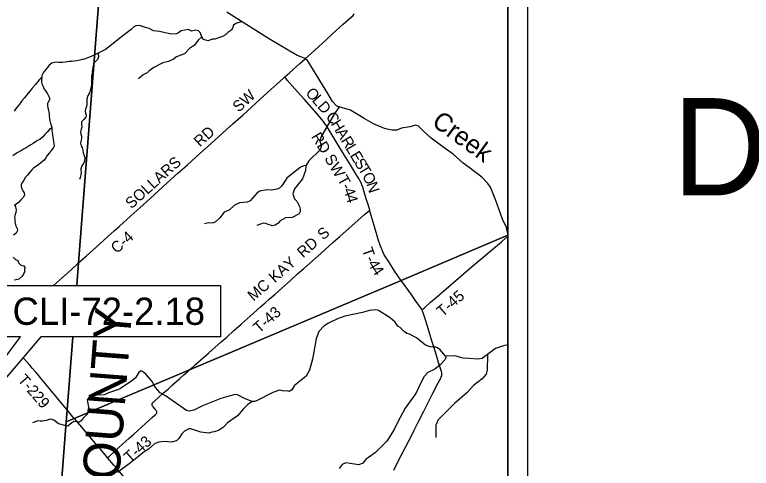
# Model space of a CAD drawing. Extents: x 0 to 34, y 0 to 22.
# Drawn here: x 6.367 to 10.15, y 18.098 to 20.428 of the extents above; entities that cross this region are included whole.
import ezdxf

# ---------------------------------------------------------------- set-up
doc = ezdxf.new("R2010")
doc.units = 0
for name, color, linetype in [('Default', 7, 'Continuous'), ('GM_X_County_Road', 7, 'Continuous'), ('GM_X_County_Road_Text', 7, 'Continuous'), ('GM_X_County_Text', 7, 'Continuous'), ('GM_X_Minor_River', 7, 'Continuous'), ('GM_X_Minor_River_Text', 7, 'Continuous'), ('GM_X_Township_Road', 7, 'Continuous'), ('GM_X_Township_Road_Text', 7, 'Continuous'), ('SH_Cut_Line', 7, 'Continuous'), ('SH_Data', 7, 'Continuous'), ('SH_Text', 7, 'Continuous')]:
    doc.layers.add(name, color=color, linetype=linetype)

msp = doc.modelspace()

# ---------------------------------------------------------------- linework, layer by layer
at = {"layer": 'Default'}
for points in [[(6.6858, 19.0362), (6.6949, 19.1537), (6.8302, 20.9), (3.1229, 20.9), (2.9275, 20.8467), (2.2946, 20.6707), (2.1, 20.6202), (2.1, 17.1279), (2.1211, 17.1003), (3.2076, 15.5689), (3.4902, 15.1704), (4.0558, 14.3671), (4.1658, 14.2105), (4.302, 14.3105), (5.6165, 15.2674), (6.0871, 15.6176), (6.2834, 15.7529), (6.4392, 15.8657), (6.5428, 17.1931), (6.5451, 17.2211), (6.6309, 18.3364), (6.6363, 18.3979), (6.6654, 18.7733)], [(6.6654, 18.7733), (6.6363, 18.3979), (6.6309, 18.3364), (6.6732, 18.3539), (7.2653, 18.6041), (8.3519, 19.0632), (8.9, 19.2947), (8.9, 20.9), (6.8302, 20.9), (6.6949, 19.1537), (6.6858, 19.0362)]]:
    msp.add_lwpolyline(points, dxfattribs=at)
msp.add_lwpolyline([(8.9, 15.8067), (8.9, 19.2947), (8.3519, 19.0632), (7.2653, 18.6041), (6.6732, 18.3539), (6.6309, 18.3364), (6.5451, 17.2211), (6.5428, 17.1931), (6.4392, 15.8657), (6.5786, 15.8624), (7.3679, 15.8435), (8.1324, 15.8252)], close=True, dxfattribs=at)
at = {"layer": 'GM_X_County_Road'}
for points in [[(7.7542, 20.1084), (7.7776, 20.1293), (7.8307, 20.1771), (7.8584, 20.202), (7.8907, 20.2312), (7.9644, 20.2978), (8.0012, 20.3312), (8.0541, 20.3792), (8.0821, 20.4039), (8.0959, 20.4164), (8.1047, 20.4252), (8.1109, 20.4321)], [(6.6951, 19.1531), (6.735, 19.1889), (6.8019, 19.2493), (6.8411, 19.2847), (6.8781, 19.3179), (6.9035, 19.3407), (6.9637, 19.3946), (7.0096, 19.4365), (7.0624, 19.4845), (7.1499, 19.5638), (7.2054, 19.6136), (7.2538, 19.6572), (7.3186, 19.7153), (7.3763, 19.7672), (7.4546, 19.8382), (7.4868, 19.8674), (7.538, 19.9127), (7.5587, 19.9314), (7.6276, 19.9941), (7.683, 20.044), (7.713, 20.0711), (7.7475, 20.1024), (7.7542, 20.1084)], [(6.6734, 18.3534), (6.6714, 18.3558), (6.6365, 18.3974)], [(6.8443, 18.1514), (6.84, 18.1565), (6.8077, 18.1951), (6.7824, 18.2248), (6.7536, 18.2586), (6.7281, 18.2885), (6.7012, 18.3201), (6.6734, 18.3534)], [(7.1522, 17.7843), (7.1477, 17.7899), (7.1124, 17.8328), (7.0863, 17.8644), (7.0586, 17.898), (7.0311, 17.9314), (6.9967, 17.972), (6.9634, 18.0116), (6.9288, 18.0526), (6.901, 18.0848), (6.8762, 18.1141), (6.8443, 18.1514)]]:
    msp.add_lwpolyline(points, dxfattribs=at)
at = {"layer": 'GM_X_Minor_River'}
for points in [[(8.9, 19.3003), (8.8996, 19.3025), (8.8927, 19.3352), (8.8716, 19.3779), (8.8389, 19.4739), (8.8104, 19.5417), (8.7974, 19.5616), (8.767, 19.5941), (8.7004, 19.6437), (8.6704, 19.6661), (8.6197, 19.7125), (8.5719, 19.7441), (8.5068, 19.7948), (8.4644, 19.8309), (8.4397, 19.8578), (8.4279, 19.8613), (8.3968, 19.8525), (8.3531, 19.8457), (8.3417, 19.8409), (8.3291, 19.8354), (8.3041, 19.8349), (8.267, 19.844), (8.2093, 19.8681), (8.161, 19.8944), (8.0925, 19.9387), (8.0211, 19.9584), (7.9997, 19.9829), (7.9759, 20.023), (7.8887, 20.1662), (7.8704, 20.1925), (7.8569, 20.2029), (7.8414, 20.2095), (7.8169, 20.2185), (7.6704, 20.3054), (7.4806, 20.4261), (7.4573, 20.4423)], [(7.5296, 20.3921), (7.5021, 20.383), (7.4903, 20.3751), (7.4821, 20.3506), (7.4622, 20.3375), (7.4503, 20.3255), (7.4351, 20.3169), (7.3951, 20.3021), (7.3822, 20.3034), (7.3586, 20.2938), (7.3367, 20.3008), (7.3278, 20.3142), (7.3196, 20.3363), (7.3107, 20.3463), (7.2974, 20.349), (7.2746, 20.3447), (7.2595, 20.3517), (7.2227, 20.3464), (7.2086, 20.3348), (7.1975, 20.3296), (7.1698, 20.328), (7.1101, 20.343), (7.0805, 20.3463), (7.0583, 20.3568), (7.033, 20.3643), (7.0088, 20.3725), (6.9887, 20.3708), (6.9788, 20.3656), (6.9654, 20.3517), (6.9222, 20.3206), (6.8495, 20.2614), (6.8327, 20.2491), (6.7779, 20.2222)], [(7.3278, 20.3142), (7.309, 20.2977), (7.2909, 20.2713), (7.2646, 20.2541), (7.2396, 20.2271), (7.1981, 20.2127), (7.1821, 20.2), (7.1573, 20.1881), (7.1281, 20.1819), (7.0819, 20.1574), (7.0571, 20.1402), (7.0468, 20.1289), (7.0266, 20.1188), (7.0021, 20.0982)], [(6.7779, 20.2222), (6.7626, 20.2146), (6.7508, 20.2097), (6.7382, 20.2049), (6.7249, 20.2008), (6.7131, 20.1975), (6.7009, 20.1949), (6.6861, 20.192), (6.6713, 20.1894), (6.658, 20.1888), (6.6466, 20.1877), (6.6359, 20.1871), (6.6257, 20.1849), (6.612, 20.1831), (6.6025, 20.1827), (6.5911, 20.1836), (6.5816, 20.184), (6.5713, 20.1834), (6.5576, 20.1789), (6.5443, 20.1695), (6.5347, 20.1574), (6.5236, 20.1431), (6.5136, 20.1295), (6.507, 20.1159), (6.5058, 20.106), (6.5049, 20.0935), (6.5045, 20.0836), (6.507, 20.073), (6.5123, 20.0623), (6.5186, 20.0463), (6.5261, 20.0349), (6.5347, 20.0215), (6.543, 20.0085), (6.5467, 19.9945), (6.5405, 19.9816), (6.5362, 19.9714), (6.5362, 19.9619), (6.5372, 19.9505), (6.5402, 19.9379), (6.5427, 19.9277), (6.5434, 19.9182), (6.5437, 19.9072), (6.5451, 19.8954), (6.5481, 19.8824), (6.5506, 19.8695), (6.5558, 19.8562), (6.5573, 19.8467), (6.5576, 19.8341), (6.5586, 19.8224), (6.5604, 19.8129), (6.5634, 19.7992), (6.5652, 19.7866), (6.5688, 19.7661), (6.5691, 19.7532), (6.5644, 19.7418), (6.5549, 19.7309), (6.5445, 19.7169), (6.5338, 19.7052), (6.5268, 19.6928), (6.518, 19.6814), (6.5073, 19.672), (6.4916, 19.6592), (6.4787, 19.6506), (6.466, 19.6408), (6.4561, 19.6337), (6.4439, 19.6197), (6.4327, 19.6038), (6.4228, 19.5929), (6.4132, 19.5789), (6.4066, 19.5683), (6.4004, 19.5551), (6.4004, 19.5452), (6.4033, 19.5331), (6.4089, 19.5235), (6.416, 19.5125), (6.4167, 19.5026), (6.4125, 19.4912), (6.3979, 19.4765), (6.3857, 19.4633), (6.3746, 19.4543), (6.3639, 19.4468)], [(6.7962, 20.2312), (6.7965, 20.2271), (6.7978, 20.2119), (6.7943, 20.1998), (6.7747, 20.1803)], [(6.7747, 20.1803), (6.7729, 20.1762), (6.7706, 20.1663), (6.769, 20.1561), (6.7666, 20.1451), (6.765, 20.1348), (6.7642, 20.1246), (6.7622, 20.1125), (6.7613, 20.103), (6.7609, 20.0923), (6.7607, 20.0692), (6.7602, 20.0589), (6.7571, 20.0457), (6.7536, 20.0317), (6.7478, 20.0195), (6.7416, 20.0093), (6.7369, 19.9942), (6.7376, 19.9801), (6.7379, 19.9684), (6.7363, 19.9574), (6.7305, 19.9437), (6.7281, 19.9339), (6.7314, 19.9217), (6.7336, 19.9118), (6.732, 19.9016), (6.7221, 19.8895), (6.7106, 19.8782), (6.7093, 19.8653), (6.7111, 19.8512), (6.7088, 19.841), (6.7056, 19.8262), (6.7059, 19.8141), (6.7096, 19.8045), (6.7099, 19.7928), (6.706, 19.7788), (6.7055, 19.7685), (6.7088, 19.7552), (6.7133, 19.7457), (6.7163, 19.7324), (6.7192, 19.7187), (6.724, 19.705), (6.7266, 19.6932), (6.7253, 19.6765), (6.721, 19.6632), (6.7111, 19.6511), (6.706, 19.6371), (6.7067, 19.6276), (6.7085, 19.617), (6.7073, 19.6056), (6.703, 19.5912), (6.6999, 19.581)], [(6.506, 20.1077), (6.4936, 20.0959), (6.484, 20.0834), (6.4736, 20.0698), (6.4575, 20.0513), (6.4456, 20.0374), (6.4364, 20.0253), (6.4268, 20.0151), (6.4169, 20.0015), (6.4042, 19.9856), (6.3969, 19.9758), (6.3858, 19.9615), (6.3747, 19.9479), (6.3647, 19.9324)], [(8.0337, 19.9543), (8.0081, 19.9168), (7.9386, 19.7984), (7.9339, 19.7791), (7.9423, 19.7558), (7.9364, 19.7347), (7.8782, 19.6772), (7.8627, 19.6523), (7.8598, 19.6281), (7.8457, 19.5846), (7.8035, 19.5342), (7.7948, 19.5073), (7.8033, 19.4829), (7.8153, 19.471), (7.8298, 19.4432), (7.8338, 19.4284), (7.8325, 19.4162), (7.8282, 19.4045), (7.7916, 19.3855), (7.7583, 19.3844), (7.7312, 19.3687), (7.7193, 19.3555), (7.7055, 19.3462), (7.6911, 19.3437), (7.6688, 19.3496), (7.656, 19.3558), (7.6439, 19.3574), (7.6108, 19.346)], [(6.5572, 19.8475), (6.5455, 19.838), (6.534, 19.8256), (6.5217, 19.8124), (6.5102, 19.7999), (6.4957, 19.7875), (6.4842, 19.7812), (6.4732, 19.7748), (6.461, 19.7658), (6.4491, 19.7598), (6.4369, 19.7515), (6.4251, 19.7451), (6.4125, 19.738), (6.4018, 19.7301), (6.3919, 19.7249), (6.3805, 19.7178), (6.3698, 19.7114), (6.3568, 19.7031)], [(7.8627, 19.6523), (7.8556, 19.6543), (7.835, 19.645), (7.7654, 19.5892), (7.7396, 19.5488), (7.7262, 19.5368), (7.7136, 19.5324), (7.6866, 19.5274), (7.6624, 19.5291), (7.6259, 19.5219), (7.6118, 19.5137), (7.5757, 19.4724), (7.5605, 19.4653), (7.521, 19.4623), (7.4947, 19.4474), (7.4706, 19.4264), (7.4436, 19.4145), (7.4205, 19.3848), (7.3991, 19.3649), (7.3876, 19.3585), (7.3743, 19.3564), (7.3619, 19.3588), (7.3417, 19.3545)], [(6.3698, 19.451), (6.371, 19.4395), (6.3744, 19.4258), (6.372, 19.4126), (6.3692, 19.4016), (6.3668, 19.3887), (6.3675, 19.3761), (6.3682, 19.3663), (6.3696, 19.3556), (6.3729, 19.3427), (6.38, 19.329), (6.3807, 19.3187), (6.3753, 19.3051), (6.3615, 19.2949)], [(6.3588, 19.1829), (6.3716, 19.1711), (6.3829, 19.1649), (6.3881, 19.1516), (6.3991, 19.1413), (6.4131, 19.1385), (6.4195, 19.129), (6.4179, 19.1172), (6.4174, 19.1066), (6.412, 19.0956), (6.4039, 19.0828), (6.3875, 19.0696), (6.3738, 19.0659), (6.3643, 19.0644)], [(8.9, 18.7312), (8.8995, 18.7315), (8.8767, 18.7275), (8.8371, 18.7124), (8.7676, 18.6611), (8.7444, 18.6576), (8.7009, 18.6618), (8.6709, 18.6636), (8.6267, 18.6755), (8.5801, 18.674), (8.5516, 18.707), (8.5392, 18.7173), (8.5294, 18.7193), (8.5161, 18.7202), (8.501, 18.7211), (8.4768, 18.7301), (8.4302, 18.7678), (8.3952, 18.7867), (8.3812, 18.7899), (8.3687, 18.7984), (8.3474, 18.8206), (8.3353, 18.8287), (8.3208, 18.8478), (8.2948, 18.8708), (8.2353, 18.9079), (8.2217, 18.911), (8.1872, 18.9076), (8.1655, 18.901), (8.1537, 18.8981), (8.0633, 18.8789), (8.0249, 18.8656), (7.9788, 18.8426), (7.954, 18.8276), (7.9286, 18.7998), (7.9161, 18.7635), (7.896, 18.659), (7.8806, 18.6023), (7.8636, 18.5709), (7.8036, 18.5237), (7.7905, 18.5011), (7.7767, 18.4929), (7.7658, 18.4953), (7.7517, 18.4943), (7.7271, 18.4983), (7.6933, 18.4873), (7.6094, 18.4445), (7.5984, 18.4401), (7.5862, 18.4402), (7.5645, 18.4256), (7.5396, 18.4016), (7.5119, 18.367), (7.4592, 18.3319), (7.4389, 18.3089), (7.4129, 18.291), (7.3912, 18.2847), (7.3798, 18.2837), (7.3646, 18.2786), (7.323, 18.2824), (7.2724, 18.3004), (7.261, 18.3009), (7.2389, 18.2882), (7.2262, 18.2754), (7.2096, 18.2509), (7.1981, 18.2385), (7.1727, 18.2316), (7.1348, 18.2354), (7.1071, 18.2326), (7.0862, 18.2245), (7.0536, 18.1956), (7.0265, 18.178), (7.0127, 18.1664), (6.9626, 18.1248), (6.8954, 18.0758)], [(8.5801, 18.674), (8.5819, 18.6661), (8.5772, 18.6559), (8.5527, 18.6288), (8.5248, 18.6074), (8.4893, 18.5896), (8.4698, 18.5693), (8.4531, 18.5365), (8.4271, 18.4821), (8.3717, 18.406), (8.3334, 18.3332), (8.3167, 18.2962), (8.2778, 18.2363), (8.2206, 18.1784), (8.1836, 18.153), (8.1737, 18.1485), (8.1545, 18.1245), (8.1351, 18.1159), (8.0684, 18.1257), (8.049, 18.1176), (8.034, 18.0957)], [(8.7952, 18.6824), (8.7942, 18.6017), (8.7887, 18.5816), (8.768, 18.5568), (8.724, 18.5231), (8.6899, 18.4851), (8.6256, 18.4304), (8.5413, 18.3459), (8.53, 18.3194), (8.5293, 18.2561)], [(7.5862, 18.4402), (7.5466, 18.4565), (7.5119, 18.4744), (7.4975, 18.4764), (7.4249, 18.4555), (7.3309, 18.4185), (7.2878, 18.3966), (7.2639, 18.3919), (7.2499, 18.3951), (7.1423, 18.4701), (7.1136, 18.4849), (7.09, 18.5128), (7.0777, 18.5334), (7.0733, 18.5429), (7.0415, 18.5797), (7.0291, 18.5912), (7.0163, 18.5978), (7.0037, 18.5892), (6.9867, 18.5628), (6.9733, 18.55), (6.9103, 18.507), (6.8996, 18.5018), (6.8532, 18.4871), (6.8258, 18.4749), (6.8019, 18.4725), (6.778, 18.4754), (6.7567, 18.471), (6.7387, 18.4488), (6.7473, 18.4006), (6.7456, 18.3877), (6.7383, 18.3745), (6.718, 18.3553), (6.7091, 18.3418), (6.6973, 18.3347), (6.6711, 18.3372), (6.6601, 18.3313), (6.6393, 18.3148), (6.6302, 18.3163)], [(6.6302, 18.3163), (6.6173, 18.3188), (6.6052, 18.3227), (6.5923, 18.3266), (6.5814, 18.3351), (6.5678, 18.3446), (6.5541, 18.3497), (6.5435, 18.3486), (6.5298, 18.3438), (6.5203, 18.3412), (6.5089, 18.339), (6.4986, 18.3402), (6.485, 18.3411), (6.472, 18.337), (6.4587, 18.3318)]]:
    msp.add_lwpolyline(points, dxfattribs=at)
at = {"layer": 'GM_X_Township_Road'}
for points in [[(8.1902, 19.4248), (8.1819, 19.4525), (8.1727, 19.4822), (8.1605, 19.524), (8.1549, 19.5418), (8.1505, 19.5534), (8.1456, 19.5648), (8.1401, 19.5759), (8.1341, 19.5868), (8.1244, 19.6027), (8.0934, 19.6529), (8.0512, 19.7219), (8.0269, 19.7616), (7.9961, 19.812), (7.9686, 19.8571), (7.96, 19.87), (7.9527, 19.88), (7.9429, 19.8921), (7.9183, 19.9201), (7.8549, 19.9926), (7.8199, 20.0322), (7.7666, 20.0929), (7.7587, 20.1025), (7.7568, 20.1049), (7.7542, 20.1084)], [(7.2811, 18.6177), (7.2952, 18.6301), (7.3232, 18.6547), (7.3626, 18.6898), (7.3952, 18.7186), (7.4279, 18.7473), (7.4558, 18.772), (7.493, 18.805), (7.5298, 18.8384), (7.5604, 18.8648), (7.5767, 18.8792), (7.6302, 18.9265), (7.6557, 18.9492), (7.6743, 18.9658), (7.7046, 18.9925), (7.7393, 19.0236), (7.7858, 19.0648), (7.8203, 19.0961), (7.8528, 19.1249), (7.911, 19.1764), (7.9387, 19.2014), (8.0013, 19.2572), (8.0361, 19.2882), (8.1317, 19.3724), (8.1641, 19.4015), (8.1826, 19.418), (8.1902, 19.4248)], [(8.3367, 19.0844), (8.3355, 19.086), (8.3198, 19.1091), (8.2826, 19.1664), (8.2712, 19.1849), (8.2636, 19.1985), (8.2581, 19.2096), (8.2518, 19.2238), (8.2459, 19.2382), (8.2417, 19.2499), (8.2362, 19.2677), (8.2133, 19.3452), (8.1935, 19.4139), (8.1902, 19.4248)], [(8.4585, 18.9127), (8.463, 18.916), (8.4655, 18.9178), (8.4727, 18.9237), (8.5029, 18.9505), (8.5335, 18.977), (8.5687, 19.0075), (8.6108, 19.0444), (8.6438, 19.0728), (8.6723, 19.0969), (8.6982, 19.1192), (8.7196, 19.1371), (8.741, 19.1552), (8.7719, 19.1813), (8.8053, 19.2092), (8.8668, 19.2616), (8.9, 19.2902)], [(6.567, 19.0362), (6.6583, 19.1194), (6.6863, 19.145), (6.6951, 19.1531)], [(8.3521, 19.0626), (8.3372, 19.0836), (8.3367, 19.0844)], [(8.4585, 18.9127), (8.4565, 18.9166), (8.4514, 18.9244), (8.4241, 18.9622), (8.4024, 18.9925), (8.3751, 19.0303), (8.3521, 19.0626)], [(8.3138, 18.088), (8.3337, 18.1267), (8.3747, 18.2069), (8.4043, 18.265), (8.4184, 18.2927), (8.4394, 18.3344), (8.466, 18.387), (8.4996, 18.4536), (8.5151, 18.4841), (8.5423, 18.5365), (8.5554, 18.5612), (8.558, 18.5669), (8.56, 18.5728), (8.5607, 18.5758), (8.5611, 18.5788), (8.5613, 18.5819), (8.5612, 18.585), (8.5609, 18.5881), (8.5596, 18.5941), (8.5559, 18.606), (8.5444, 18.6415), (8.5296, 18.6889), (8.5174, 18.7275), (8.5084, 18.7572), (8.4956, 18.7988), (8.4782, 18.8552), (8.465, 18.8966), (8.4619, 18.9054), (8.4594, 18.9111), (8.4585, 18.9127)], [(6.6365, 18.3974), (6.6264, 18.4097), (6.5989, 18.4426), (6.5845, 18.4598), (6.5568, 18.4933), (6.5509, 18.5005), (6.5248, 18.5321), (6.5002, 18.5618), (6.4871, 18.5775), (6.4758, 18.5908), (6.4572, 18.6124), (6.4441, 18.6274), (6.4306, 18.6428), (6.4103, 18.666)], [(7.2655, 18.6036), (7.2789, 18.6157), (7.2811, 18.6177)], [(6.8443, 18.1514), (6.8476, 18.1542), (6.8522, 18.1584), (6.8819, 18.1857), (6.9231, 18.2234), (6.9529, 18.2505), (6.9781, 18.2734), (7.0382, 18.3272), (7.075, 18.3605), (7.0892, 18.3727), (7.0915, 18.3748), (7.0935, 18.3771), (7.0952, 18.3797), (7.0963, 18.3825), (7.0967, 18.3854), (7.0964, 18.3885), (7.0955, 18.3913), (7.0941, 18.3941), (7.0923, 18.3967), (7.0904, 18.3992), (7.0778, 18.4131), (7.0759, 18.4156), (7.0742, 18.4182), (7.0729, 18.4209), (7.0722, 18.4238), (7.0722, 18.4268), (7.073, 18.4297), (7.0744, 18.4324), (7.0764, 18.4349), (7.0785, 18.4371), (7.0831, 18.4414), (7.1087, 18.4639), (7.1319, 18.4845), (7.1552, 18.505), (7.1783, 18.5257), (7.2153, 18.5587), (7.2361, 18.5773), (7.2546, 18.5939), (7.2655, 18.6036)]]:
    msp.add_lwpolyline(points, dxfattribs=at)
at = {"layer": 'SH_Cut_Line'}
for points in [[(6.6858, 19.0362), (6.6949, 19.1537), (6.8302, 20.9), (2.1, 20.9), (2.1, 14.1), (4.022, 14.1), (4.1658, 14.2105), (4.302, 14.3105), (5.6165, 15.2674), (6.0871, 15.6176), (6.2834, 15.7529), (6.4392, 15.8657), (6.5428, 17.1931), (6.5451, 17.2211), (6.6309, 18.3364), (6.6363, 18.3979), (6.6654, 18.7733)], [(6.6654, 18.7733), (6.6363, 18.3979), (6.6309, 18.3364), (6.5451, 17.2211), (6.5428, 17.1931), (6.4392, 15.8657), (6.5786, 15.8624), (7.3679, 15.8435), (8.1324, 15.8252), (8.9, 15.8067), (8.9, 20.9), (6.8302, 20.9), (6.6949, 19.1537), (6.6858, 19.0362)]]:
    msp.add_lwpolyline(points, dxfattribs=at)
at = {"layer": 'SH_Data'}
for p, q in [((9, 21), (9, 14)), ((8.9, 20.9), (8.9, 14.1))]:
    msp.add_line(p, q, dxfattribs=at)
at = {"layer": 'SH_Text'}
msp.add_lwpolyline([(6.2913, 19.0362), (7.4233, 19.0362), (7.4233, 18.7733), (6.5017, 18.7733), (5.6692, 17.796), (6.3965, 18.7733), (6.2913, 18.7733)], close=True, dxfattribs=at)

# ---------------------------------------------------------------- texts
at = {"layer": 'GM_X_County_Road_Text'}
for s, rotation, p in [('SW', 42.1201, (7.5173, 19.924)), ('RD', 42.1219, (7.3182, 19.7457)), ('SOLLARS', 42.0562, (6.9665, 19.4281)), ('C-4', 41.7488, (6.8913, 19.1978))]:
    msp.add_text(s, height=0.05682, rotation=rotation, dxfattribs=at).set_placement(p)
at = {"layer": 'GM_X_County_Text'}
msp.add_text('FAYETTE COUNTY', height=0.189394, rotation=85.5978, dxfattribs=at).set_placement((6.7959, 16.6433))
at = {"layer": 'GM_X_Minor_River_Text'}
msp.add_text('Creek', height=0.0947, rotation=323.972, dxfattribs=at).set_placement((8.5036, 19.8644))
at = {"layer": 'GM_X_Township_Road_Text'}
for s, height, rotation, p in [('O', 0.0568, 311.3038, (7.8575, 20.0239)), ('L', 0.0568, 311.3004, (7.8905, 19.9863)), ('D', 0.0568, 311.0482, (7.9185, 19.9544)), ('C', 0.0568, 305.9324, (7.9617, 19.9043)), ('H', 0.0568, 301.661, (7.9885, 19.8675)), ('RD SW', 0.05682, 301.2645, (7.8878, 19.8023)), ('A', 0.0568, 301.1199, (8.0146, 19.825)), ('R', 0.0568, 301.1097, (8.0405, 19.7822)), ('L', 0.0568, 301.1133, (8.0646, 19.7423)), ('E', 0.0568, 301.1161, (8.0865, 19.7059)), ('S', 0.0568, 301.1129, (8.1085, 19.6695)), ('T', 0.0568, 301.0718, (8.1283, 19.6367)), ('T', 0.0568, 299.6561, (8.0221, 19.5829)), ('O', 0.0568, 297.6077, (8.1498, 19.6011)), ('N', 0.0568, 288.0871, (8.172, 19.5591)), ('-', 0.0568, 299.4602, (8.0431, 19.546)), ('4', 0.0568, 291.1974, (8.0536, 19.5276)), ('4', 0.0568, 285.9954, (8.0658, 19.4963)), ('S', 0.0568, 40.6003, (7.951, 19.2676)), ('RD', 0.05682, 41.84, (7.8482, 19.1756)), ('T', 0.0568, 289.6466, (8.1487, 19.221)), ('KAY', 0.05682, 41.6601, (7.7032, 19.0473)), ('-', 0.0568, 296.8935, (8.1661, 19.1738)), ('4', 0.0568, 299.9516, (8.1782, 19.1501)), ('4', 0.0568, 302.8221, (8.1973, 19.1171)), ('MC', 0.05682, 41.3081, (7.5938, 18.9534)), ('T-45', 0.05682, 40.9865, (8.5645, 18.8729)), ('T-43', 0.05682, 41.5138, (7.6227, 18.7887)), ('T-229', 0.05682, 310.7576, (6.3793, 18.5499)), ('T-43', 0.05682, 42.0139, (6.9592, 18.1234))]:
    msp.add_text(s, height=height, rotation=rotation, dxfattribs=at).set_placement(p)
at = {"layer": 'SH_Text'}
for s, height, p in [('DEPARTMENT OF TRANSPORTATION', 0.5, (9.7466, 19.5)), ('CLI-72-2.18', 0.14, (6.356, 18.8347))]:
    msp.add_text(s, height=height, dxfattribs=at).set_placement(p)

doc.saveas('drawing.dxf')
